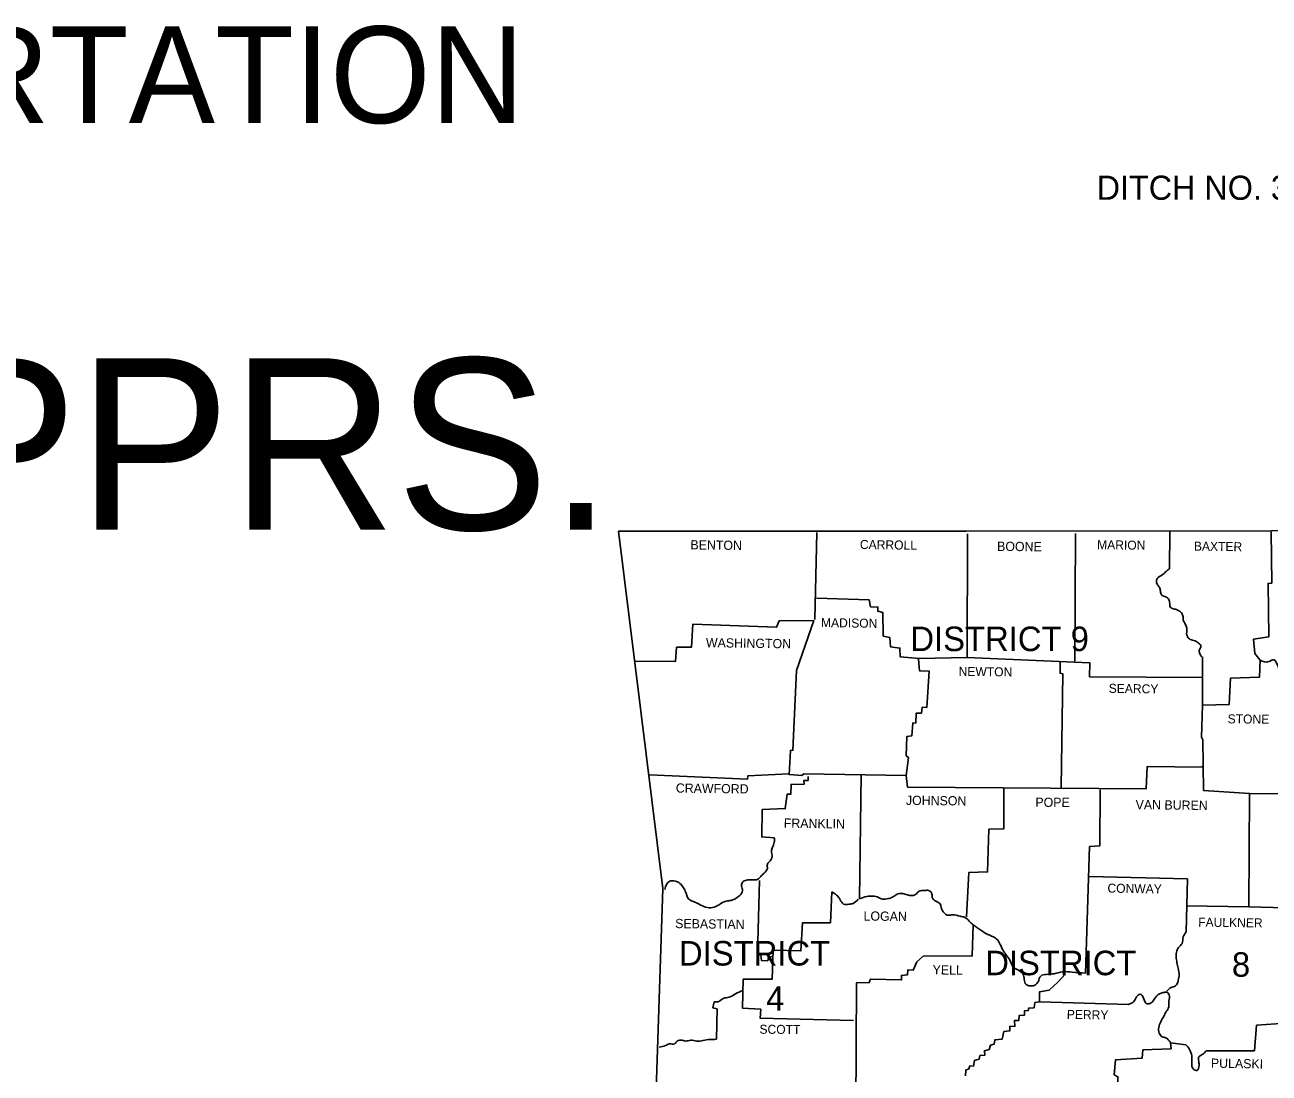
# Model space of a CAD drawing. Extents: x 171 to 3403, y 68 to 2102.
# Drawn here: x 2434 to 3000, y 1625 to 2102 of the extents above; entities that cross this region are included whole.
import ezdxf

# ---------------------------------------------------------------- set-up
doc = ezdxf.new("R2010")
doc.units = 0
for name, color, linetype in [('1', 7, 'Continuous'), ('2', 7, 'Continuous'), ('3', 7, 'Continuous'), ('R_Border', 7, 'Continuous')]:
    doc.layers.add(name, color=color, linetype=linetype)

msp = doc.modelspace()

# ---------------------------------------------------------------- linework, layer by layer
at = {"layer": '1'}
for points in [[(2703.71, 1871.91), (2861.92, 1871.81), (3000.75, 1872.1), (3164.54, 1874.65), (3240.46, 1876.41)], [(2703.71, 1871.91), (2723.96, 1709.3), (2715.15, 1443.86)], [(2794.01, 1871.32), (2793.13, 1831.7)], [(2793.82, 1841.38), (2817.89, 1840.6), (2818.47, 1837.47), (2821.8, 1837.37), (2821.7, 1835.41), (2824.05, 1834.83), (2824.25, 1824.16), (2827.28, 1823.48), (2827.48, 1819.27), (2831.78, 1818.68), (2831.98, 1814.77), (2840.49, 1813.89), (2862.4, 1814.38), (2862.6, 1870.64)], [(2911.62, 1870.83), (2911.33, 1812.72)], [(2954.67, 1871.52), (2954.47, 1854.79)], [(3000.75, 1871.52), (3000.95, 1848.23), (2999.28, 1848.13), (2999.58, 1823.77), (2992.73, 1822.79), (2993.32, 1816.24), (2995.66, 1813.2), (2995.47, 1805.48), (2982.16, 1804.99), (2981.67, 1793.05), (2969.54, 1792.66), (2968.95, 1778.18), (2969.64, 1777), (2969.93, 1753.91), (2990.87, 1752.54), (2990.58, 1700.98), (3007.21, 1700.49), (3007.21, 1648.05), (2994.1, 1647.07), (2993.12, 1635.53), (2971.11, 1635.43)], [(2711.44, 1812.72), (2729.73, 1812.62), (2730.22, 1819.08), (2736.97, 1819.08), (2737.56, 1829.54), (2775.72, 1828.17), (2776.89, 1831.11), (2792.64, 1831.21), (2784.72, 1808.51), (2783.15, 1772.21), (2781.98, 1772.11), (2781.39, 1761.15), (2787.17, 1760.66), (2788.05, 1761.54), (2834.72, 1760.66), (2835.21, 1755.48)], [(2840.29, 1813.69), (2840.68, 1808.41), (2845.18, 1808.12), (2844.01, 1791.68), (2841.96, 1791.78), (2841.56, 1789.14), (2839.22, 1789.14), (2839.12, 1784.64), (2837.65, 1784.54), (2837.16, 1778.76), (2835.01, 1778.47), (2834.72, 1769.67), (2835.69, 1768.98), (2834.72, 1760.66)], [(2862.4, 1814.38), (2918.17, 1812.03), (2918.08, 1805.67), (2969.25, 1805.28)], [(2904.77, 1812.32), (2904.67, 1807.24), (2905.94, 1806.94), (2905.16, 1755.28)], [(2969.54, 1792.66), (2969.44, 1814.67)], [(2717.89, 1761.06), (2762.41, 1759), (2762.61, 1760.57), (2781.2, 1761.45)], [(2814.17, 1761.06), (2813.48, 1704.6)], [(2835.21, 1755.48), (2943.81, 1754.6), (2944.3, 1764.87), (2969.54, 1764.58)], [(2969.25, 1764.68), (2969.54, 1764.97)], [(2790, 1760.27), (2790, 1758.51), (2788.14, 1758.51), (2788.24, 1756.75), (2782.27, 1756.65), (2782.18, 1752.25), (2780.51, 1752.25), (2779.63, 1745.69), (2769.06, 1745.21), (2768.97, 1732.78), (2774.64, 1732.39)], [(2879.14, 1754.7), (2879.04, 1736.4), (2872.29, 1736.3), (2871.7, 1716.83), (2863.09, 1716.54), (2862.11, 1696.38)], [(2922.97, 1754.21), (2922.77, 1728.77), (2918.08, 1728.38), (2916.22, 1670.85)], [(2990.87, 1752.54), (3041.16, 1752.25), (3045.46, 1754.3), (3045.17, 1716.05), (3042.24, 1714.78), (3039.59, 1712.53), (3038.71, 1711.65), (3038.62, 1700.69), (3006.62, 1700.69)], [(2767.99, 1713.02), (2767.01, 1679.36), (2768.48, 1678.97), (2768.77, 1676.62), (2771.71, 1676.42), (2772, 1678.09), (2774.35, 1678.48)], [(2917.88, 1714.78), (2962.59, 1713.7), (2962.01, 1689.53)], [(2800.86, 1707.73), (2800.18, 1693.74), (2787.46, 1693.64), (2786.77, 1680.92), (2774.15, 1681.22), (2773.76, 1668.11), (2760.55, 1668.01), (2760.16, 1654.9), (2768.48, 1654.41), (2768.18, 1650.4), (2810.65, 1649.22)], [(2962.1, 1701.37), (2990.58, 1700.98)], [(2865.14, 1692.76), (2864.75, 1678.67), (2842.45, 1678.58), (2839.51, 1676.03), (2837.85, 1672.12), (2835.4, 1672.31), (2835.3, 1670.06), (2832.47, 1669.77), (2832.56, 1667.72), (2818.38, 1668.11), (2817.89, 1666.54), (2812.02, 1666.35), (2811.82, 1609.11)], [(2907.12, 1670.46), (2903.6, 1666.64), (2899.78, 1663.02), (2895.38, 1662.33), (2895.38, 1657.74), (2893.22, 1657.44), (2892.83, 1655.09), (2890.39, 1654.9), (2890.19, 1653.82), (2888.53, 1653.72), (2888.43, 1651.67), (2886.08, 1651.57), (2885.89, 1649.22), (2883.93, 1649.22), (2884.03, 1646.48), (2881.88, 1646.68), (2881.78, 1644.53), (2879.14, 1644.33), (2878.35, 1640.81), (2875.03, 1640.52), (2874.73, 1638.56), (2872.97, 1638.07), (2872.48, 1636.02), (2870.23, 1635.53), (2870.43, 1633.47), (2868.18, 1633.28), (2867.79, 1631.71), (2865.73, 1631.12), (2865.24, 1628.48), (2863.68, 1628.58), (2863.19, 1627.21), (2861.72, 1626.72), (2861.62, 1624.08)], [(2748.32, 1640.71), (2748.62, 1654.51), (2746.66, 1655.09), (2747.25, 1657.74)], [(2935.79, 1656.56), (2895.47, 1657.83)], [(2961.91, 1638.27), (2954.86, 1639.05), (2955.16, 1636.41), (2942.34, 1635.92), (2941.95, 1632.1), (2929.91, 1631.42), (2929.23, 1624.57), (2930.99, 1623.69), (2930.99, 1619.19)], [(2992.63, 1635.62), (2993.12, 1636.11)]]:
    msp.add_lwpolyline(points, dxfattribs=at)
for points in [[(2954.47, 1854.79), (2952.71, 1853.32), (2951.15, 1851.95), (2948.8, 1850.29), (2948.5, 1848.72), (2949.29, 1847.16), (2950.07, 1845.88), (2950.36, 1844.12), (2951.05, 1842.65), (2952.71, 1842.07), (2954.08, 1840.8), (2954.57, 1839.03), (2954.77, 1837.37), (2956.33, 1836.59), (2958.09, 1836), (2959.76, 1834.83), (2960.54, 1833.36), (2960.73, 1831.5), (2961.42, 1830.03), (2962.2, 1828.27), (2962.4, 1826.8), (2962.2, 1825.34), (2962.59, 1823.97), (2963.87, 1822.6), (2966.12, 1821.91), (2967.68, 1820.93), (2968.76, 1819.56), (2968.07, 1817.9), (2968.17, 1816.43), (2969.05, 1814.67)], [(2995.66, 1813.2), (2999.58, 1812.52), (3001.93, 1813.4), (3003.59, 1810.86), (3004.47, 1808.9), (3005.94, 1806.06), (3008.29, 1805.18), (3010.05, 1803.62), (3010.05, 1801.95), (3008.48, 1800.39), (3007.31, 1798.82), (3007.7, 1796.96), (3008.09, 1794.42), (3008.09, 1791.97), (3007.5, 1789.72), (3007.01, 1787.67), (3007.5, 1785.91), (3009.36, 1786.2), (3011.32, 1787.67), (3013.37, 1787.67), (3015.33, 1786.59), (3017.38, 1784.73), (3019.44, 1785.12), (3021.1, 1785.61), (3023.45, 1786.3), (3025.11, 1785.42), (3026.58, 1784.24), (3028.34, 1782.38), (3030.01, 1781.21), (3032.16, 1780.13), (3034.8, 1779.45), (3037.25, 1777.79), (3037.64, 1774.95), (3037.54, 1772.5), (3037.34, 1769.47), (3037.15, 1766.14), (3037.44, 1762.91), (3038.52, 1760.76), (3039.89, 1758.22), (3040.28, 1755.87), (3040.18, 1752.15)], [(2774.64, 1732.39), (2774.64, 1730.33), (2773.86, 1728.18), (2773.37, 1726.32), (2773.66, 1723.88), (2772.78, 1721.92), (2771.51, 1720.35), (2771.51, 1718.4), (2770.04, 1716.34), (2768.48, 1714.78), (2767.11, 1713.51), (2764.66, 1713.31), (2762.61, 1713.21), (2760.55, 1712.53), (2759.77, 1711.06), (2760.16, 1708.81), (2759.38, 1706.66), (2757.32, 1704.99), (2755.07, 1703.92), (2752.73, 1703.53), (2749.5, 1701.96), (2746.56, 1700.69), (2743.43, 1700.88), (2740.5, 1702.16), (2737.85, 1703.33), (2735.8, 1704.5), (2734.14, 1708.12), (2733.06, 1710.08), (2731.2, 1712.04), (2728.95, 1712.82), (2727.09, 1712.62), (2724.84, 1708.81)], [(2800.86, 1707.73), (2803.02, 1706.36), (2804.68, 1704.11), (2806.15, 1702.25), (2808.59, 1702.16), (2810.55, 1702.55), (2812.8, 1704.5)], [(2813.48, 1704.6), (2816.71, 1705.68), (2819.06, 1705.87), (2821.41, 1705.48), (2823.86, 1704.5), (2826.5, 1704.7), (2828.45, 1705.38), (2830.41, 1706.66), (2832.56, 1707.05), (2834.62, 1706.66), (2836.77, 1706.07), (2839.12, 1706.75), (2840.49, 1708.03), (2842.84, 1708.42), (2844.89, 1708.42), (2846.36, 1706.75), (2846.65, 1704.99), (2848.51, 1703.33), (2850.17, 1702.25), (2850.66, 1700.2), (2851.54, 1698.73), (2852.43, 1697.75), (2853.7, 1697.17), (2855.85, 1697.36), (2859.18, 1696.68), (2861.33, 1696.19), (2863.29, 1694.52), (2865.14, 1692.76)], [(2865.14, 1692.76), (2868.57, 1690.41), (2871.8, 1688.36), (2875.12, 1686.89), (2876.98, 1684.74), (2878.65, 1681.41), (2880.02, 1679.36), (2881.78, 1676.81), (2883.05, 1673.98), (2885.1, 1672.41), (2887.26, 1671.04), (2888.33, 1668.6), (2888.82, 1666.15), (2891.17, 1664.98), (2893.42, 1665.47), (2894.69, 1666.93), (2895.87, 1669.48), (2898.51, 1670.26), (2901.93, 1670.55), (2905.85, 1671.43), (2910.15, 1671.24), (2916.22, 1670.85)], [(2962.01, 1689.53), (2960.73, 1687.28), (2960.15, 1684.35), (2958.58, 1682.49), (2957.6, 1680.34), (2957.51, 1677.5), (2958, 1674.96), (2958.48, 1672.51), (2958.88, 1670.26), (2958.39, 1667.42), (2957.11, 1664.98), (2955.16, 1664.29), (2953.3, 1662.63)], [(2747.25, 1657.74), (2749.4, 1657.93), (2751.45, 1659.3), (2754.19, 1659.89), (2756.93, 1661.36), (2760.36, 1662.92)], [(2935.79, 1656.56), (2938.23, 1657.93), (2939.5, 1659.99), (2941.07, 1661.26), (2942.63, 1659.5), (2944, 1656.95), (2945.47, 1656.95), (2947.33, 1658.71), (2948.5, 1660.28), (2949.97, 1661.45), (2951.54, 1661.94), (2953.2, 1662.14), (2954.47, 1660.28), (2954.08, 1657.34), (2954.08, 1655.39), (2953.01, 1653.33), (2951.83, 1651.18), (2950.56, 1648.73), (2949.58, 1646.09), (2949.78, 1643.55), (2951.15, 1641.89), (2952.71, 1641.4), (2954.86, 1639.24)], [(2748.32, 1640.71), (2745.49, 1640.61), (2742.26, 1640.22), (2739.32, 1639.83), (2736.68, 1640.32), (2734.23, 1639.93), (2732.57, 1640.32), (2730.52, 1639.83), (2729.34, 1638.66), (2726.9, 1638.66), (2725.13, 1637.87), (2722.3, 1637.19)], [(2961.91, 1638.27), (2963.57, 1636.11), (2964.55, 1633.18), (2964.55, 1629.85), (2965.33, 1627.11), (2966.9, 1626.52), (2967.88, 1628.87), (2967.68, 1631.22), (2967.68, 1632.59), (2969.34, 1633.76), (2971.11, 1635.43)]]:
    msp.add_spline(points, degree=3, dxfattribs=at)

# ---------------------------------------------------------------- texts
at = {"layer": '2'}
for s, height, p in [('ARKANSAS DEPARTMENT OF TRANSPORTATION', 44.03, (1260.7, 2057.5)), ('DITCH NO.  30 STR.  & APPRS.', 78, (1188.38, 1872.54))]:
    msp.add_text(s, height=height, dxfattribs=at).set_placement(p)
for s, height, rotation, p in [('BENTON', 4.207, 359.2527, (2736.48, 1863.59)), ('CARROLL', 4.109, 359.1481, (2813.58, 1863.79)), ('BOONE', 4.207, 359.4001, (2876, 1862.91)), ('MARION', 4.109, 359.1854, (2921.5, 1863.69)), ('BAXTER', 4.109, 359.2559, (2965.53, 1863.01)), ('MADISON', 4.109, 359.0906, (2795.87, 1828.27)), ('WASHINGTON', 4.206, 359.232, (2743.53, 1819.08)), ('NEWTON', 4.109, 359.2717, (2858.49, 1806.06)), ('SEARCY', 4.108, 359.2527, (2926.78, 1798.33)), ('STONE', 4.108, 359.4001, (2980.89, 1784.44)), ('CRAWFORD', 4.206, 359.2771, (2729.83, 1752.93)), ('JOHNSON', 4.207, 359.3514, (2834.52, 1747.36)), ('POPE', 4.207, 359.6155, (2893.42, 1746.48)), ('VAN BUREN', 4.207, 359.3508, (2939.01, 1745.4)), ('FRANKLIN', 4.207, 359.1815, (2778.95, 1736.99)), ('CONWAY', 4.108, 359.0371, (2926.2, 1707.44)), ('LOGAN', 4.207, 359.3969, (2815.25, 1694.72)), ('SEBASTIAN', 4.206, 359.2816, (2729.54, 1691.3)), ('FAULKNER', 4.109, 359.2486, (2967.49, 1691.98)), ('YELL', 4.207, 359.1987, (2846.65, 1670.26)), ('PERRY', 4.109, 359.0858, (2907.71, 1650.01)), ('SCOTT', 4.109, 359.4063, (2767.89, 1643.26)), ('PULASKI', 4.207, 359.053, (2973.26, 1627.8))]:
    msp.add_text(s, height=height, rotation=rotation, dxfattribs=at).set_placement(p)
at = {"layer": '3'}
for s, height, p in [('DISTRICT 9', 11.154, (2836.57, 1817.31)), ('DISTRICT', 11.154, (2731.3, 1674.27)), ('DISTRICT', 11.154, (2870.62, 1669.87)), ('8', 11.15, (2982.85, 1669.18)), ('4', 11.15, (2770.92, 1653.72))]:
    msp.add_text(s, height=height, dxfattribs=at).set_placement(p)
at = {"layer": 'R_Border'}
msp.add_text('DITCH NO. 30 STR. & APPRS. (BLYTHEVILLE) (S)', height=11, dxfattribs=at).set_placement((2921.32, 2022.61))

doc.saveas('drawing.dxf')
